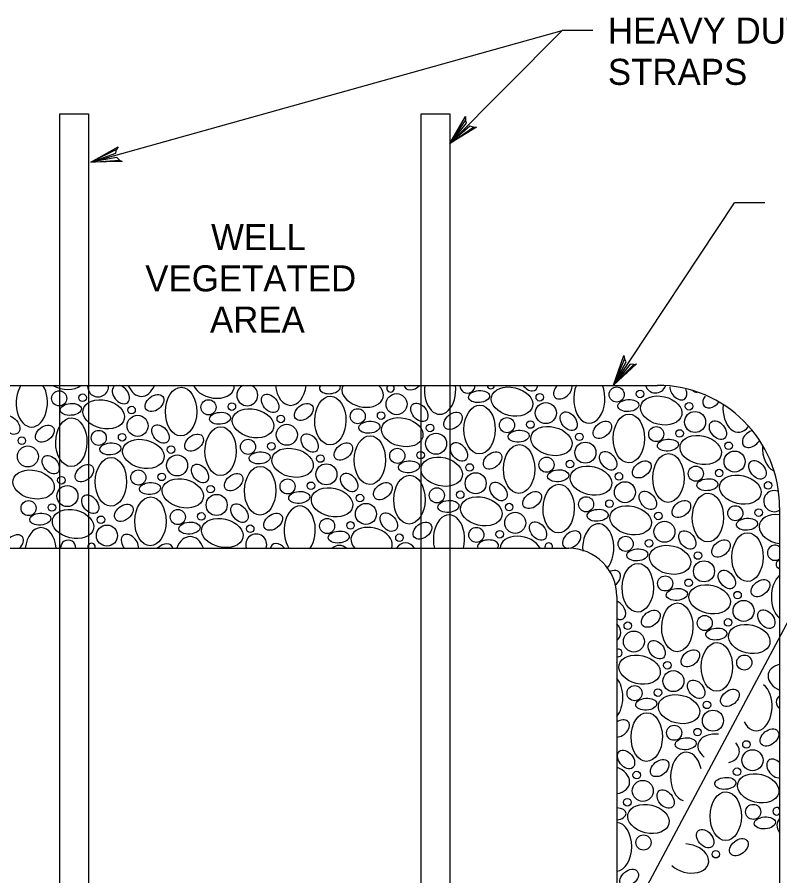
# Model space of a CAD drawing. Extents: x 636462 to 637367, y 299944 to 300538.
# Drawn here: x 636795.7 to 636883.5, y 300304.9 to 300403.7 of the extents above; entities that cross this region are included whole.
import ezdxf

# ---------------------------------------------------------------- set-up
doc = ezdxf.new("R2010")
doc.units = 0
doc.layers.add('Default', color=7, linetype='Continuous')

msp = doc.modelspace()

# ---------------------------------------------------------------- linework, layer by layer
at = {"layer": 'Default'}
for p, q in [((636804.179, 300386.976), (636858.441, 300402.116)), ((636845.491, 300389.125), (636858.441, 300402.116)), ((636861.939, 300402.116), (636858.441, 300402.116)), ((636864.326, 300361.299), (636878.253, 300382.304)), ((636881.751, 300382.304), (636878.253, 300382.304)), ((636865.698, 300299.031), (636894.027, 300352.145)), ((636786.81, 300342.561), (636859.157, 300342.561)), ((636800.614, 300342.561), (636803.895, 300342.561)), ((636842.21, 300342.561), (636845.491, 300342.561)), ((636864.722, 300336.996), (636864.722, 300303.181))]:
    msp.add_line(p, q, dxfattribs=at)
for points in [[(636800.614, 300342.561), (636800.614, 300392.536), (636803.895, 300392.536), (636803.895, 300342.561)], [(636842.21, 300342.561), (636842.21, 300392.536), (636845.491, 300392.536), (636845.491, 300342.561)], [(636848.209, 300390.986), (636848.557, 300391.021), (636845.491, 300389.125), (636848.209, 300390.986), (636847.805, 300391.106), (636845.491, 300389.125), (636847.427, 300391.469), (636847.287, 300391.862), (636845.491, 300389.125), (636847.303, 300392.241), (636847.287, 300391.862)], [(636807.465, 300387.201), (636807.783, 300387.055), (636804.179, 300386.976), (636807.465, 300387.201), (636807.179, 300387.51), (636804.179, 300386.976), (636807.037, 300388.014), (636807.115, 300388.424), (636804.179, 300386.976), (636807.322, 300388.742), (636807.115, 300388.424)], [(636866.664, 300363.681), (636866.998, 300363.783), (636864.354, 300361.332), (636866.664, 300363.681), (636866.244, 300363.722), (636864.354, 300361.332), (636865.804, 300364.005), (636865.59, 300364.364), (636864.354, 300361.332), (636865.534, 300364.739), (636865.59, 300364.364)], [(636776.561, 300361.299), (636869.406, 300361.299)], [(636883.459, 300347.245), (636883.459, 300282.226)], [(636800.614, 300286.91), (636800.614, 300342.561)], [(636803.895, 300342.561), (636803.895, 300286.91)], [(636842.21, 300286.91), (636842.21, 300342.561)], [(636845.491, 300342.561), (636845.491, 300286.91)]]:
    msp.add_lwpolyline(points, dxfattribs=at)
for centre, radius in [((636800.529, 300359.801), 0.869), ((636803.221, 300359.874), 0.435), ((636839.363, 300359.135), 1.211), ((636855.85, 300359.924), 0.435), ((636864.705, 300360.241), 0.869), ((636867.396, 300360.314), 0.435), ((636817.712, 300358.773), 0.869), ((636856.545, 300358.107), 1.211), ((636873.032, 300358.896), 0.435), ((636808.856, 300358.456), 0.435), ((636820.403, 300358.846), 0.435), ((636834.894, 300357.745), 0.869), ((636809.552, 300356.639), 1.211), ((636826.038, 300357.428), 0.435), ((636837.585, 300357.818), 0.435), ((636852.076, 300356.717), 0.869), ((636873.727, 300357.078), 1.211), ((636826.734, 300355.61), 1.211), ((636843.221, 300356.4), 0.435), ((636854.767, 300356.789), 0.435), ((636869.258, 300355.688), 0.869), ((636796.227, 300354.932), 0.435), ((636805.082, 300355.249), 0.869), ((636807.773, 300355.321), 0.435), ((636843.916, 300354.582), 1.211), ((636860.403, 300355.372), 0.435), ((636871.949, 300355.761), 0.435), ((636822.264, 300354.22), 0.869), ((636824.955, 300354.293), 0.435), ((636861.098, 300353.554), 1.211), ((636877.585, 300354.343), 0.435), ((636796.922, 300353.114), 1.211), ((636813.409, 300353.904), 0.435), ((636839.446, 300353.192), 0.869), ((636842.137, 300353.265), 0.435), ((636878.28, 300352.526), 1.211), ((636814.104, 300352.086), 1.211), ((636830.591, 300352.875), 0.435), ((636856.628, 300352.164), 0.869), ((636859.319, 300352.237), 0.435), ((636809.635, 300350.696), 0.869), ((636831.286, 300351.058), 1.211), ((636847.773, 300351.847), 0.435), ((636873.81, 300351.136), 0.869), ((636876.501, 300351.209), 0.435), ((636800.779, 300350.379), 0.435), ((636812.326, 300350.769), 0.435), ((636826.817, 300349.668), 0.869), ((636848.468, 300350.03), 1.211), ((636864.955, 300350.819), 0.435), ((636801.475, 300348.562), 1.211), ((636817.962, 300349.351), 0.435), ((636829.508, 300349.741), 0.435), ((636843.999, 300348.64), 0.869), ((636865.65, 300349.001), 1.211), ((636882.137, 300349.791), 0.435), ((636818.657, 300347.533), 1.211), ((636835.144, 300348.323), 0.435), ((636846.69, 300348.712), 0.435), ((636861.181, 300347.612), 0.869), ((636797.005, 300347.172), 0.869), ((636799.696, 300347.244), 0.435), ((636835.839, 300346.505), 1.211), ((636852.326, 300347.295), 0.435), ((636863.872, 300347.684), 0.435), ((636878.363, 300346.583), 0.869), ((636814.187, 300346.143), 0.869), ((636816.878, 300346.216), 0.435), ((636853.021, 300345.477), 1.211), ((636869.508, 300346.267), 0.435), ((636881.054, 300346.656), 0.435), ((636805.332, 300345.827), 0.435), ((636831.369, 300345.115), 0.869), ((636834.06, 300345.188), 0.435), ((636870.203, 300344.449), 1.211), ((636806.027, 300344.009), 1.211), ((636822.514, 300344.798), 0.435), ((636848.551, 300344.087), 0.869), ((636851.242, 300344.16), 0.435), ((636839.696, 300343.77), 0.435), ((636865.733, 300343.059), 0.869), ((636868.424, 300343.132), 0.435), ((636874.06, 300341.714), 0.435), ((636874.755, 300339.896), 1.211), ((636870.286, 300338.506), 0.869), ((636872.977, 300338.579), 0.435), ((636878.613, 300337.161), 0.435), ((636879.308, 300335.344), 1.211), ((636874.838, 300333.954), 0.869), ((636865.983, 300333.637), 0.435), ((636877.53, 300334.027), 0.435), ((636866.679, 300331.819), 1.211), ((636879.391, 300329.401), 0.869), ((636870.536, 300329.084), 0.435), ((636871.231, 300327.267), 1.211), ((636866.761, 300325.877), 0.869), ((636869.453, 300325.95), 0.435), ((636875.088, 300324.532), 0.435), ((636875.784, 300322.714), 1.211), ((636871.314, 300321.324), 0.869), ((636874.005, 300321.397), 0.435), ((636879.641, 300319.979), 0.435), ((636880.336, 300318.162), 1.211), ((636867.011, 300316.455), 0.435), ((636878.558, 300316.845), 0.435), ((636867.707, 300314.637), 1.211), ((636865.928, 300313.32), 0.435), ((636880.419, 300312.219), 0.869), ((636867.79, 300308.695), 0.869), ((636876.117, 300307.35), 0.435)]:
    msp.add_circle(centre, radius, dxfattribs=at)
for centre, radius, start, end in [((636804.999, 300361.191), 1.211, 174.90177, 5.09823), ((636822.181, 300360.163), 1.211, 110.34202, 69.65798), ((636838.668, 300360.952), 0.435, 127.15322, 52.84678), ((636847.523, 300361.269), 0.869, 178.05212, 1.94788), ((636850.214, 300361.342), 0.435, 185.70515, 354.29485), ((636869.175, 300361.631), 1.211, 195.91853, 340.57424), ((636869.406, 300347.245), 14.053, 360, 90), ((636882.832, 300347.973), 1.211, 71.40593, 301.16664), ((636823.209, 300342.981), 1.211, 339.72002, 200.27998), ((636801.558, 300342.619), 0.869, 356.16847, 183.83153), ((636804.249, 300342.692), 0.435, 342.48017, 197.51983), ((636840.391, 300341.953), 1.211, 30.14319, 149.85681), ((636856.878, 300342.742), 0.435, 335.36934, 204.63066), ((636859.157, 300336.996), 5.565, 0, 90), ((636882.915, 300342.031), 0.869, 51.25813, 308.74187), ((636864.9, 300330.502), 0.435, 245.75739, 114.24261), ((636883.944, 300324.849), 0.869, 123.85392, 236.14608), ((636883.11, 300312.292), 0.435, 36.56425, 323.43575)]:
    msp.add_arc(centre, radius, start, end, dxfattribs=at)
for centre, major_axis, ratio, start_param, end_param in [((636797.375, 300359.305), (0.03, 2.806), 0.641702, 0.787152, 5.509543), ((636801.101, 300362.517), (-2.359, 0.554), 0.672414, 1.147145, 2.666394), ((636807.628, 300360.252), (-0.766, 0.938), 0.672414, 5.99084, 11.854683), ((636810.004, 300362.829), (0.03, 2.806), 0.641702, 2.154377, 4.142318), ((636818.283, 300361.489), (-2.359, 0.554), 0.672414, 0.449253, 3.364286), ((636827.186, 300361.801), (0.03, 2.806), 0.641702, 1.757474, 4.53922), ((636831.68, 300361.029), (1.211, 0.089), 0.56568, 2.61181, 6.555696), ((636835.465, 300360.46), (-2.359, 0.554), 0.672414, 6.096692, 10.283218), ((636841.313, 300361.758), (0.938, 0.766), 0.672414, 2.741076, 4.920143), ((636844.368, 300360.773), (0.03, 2.806), 0.641702, 1.388977, 4.907717), ((636854.622, 300361.72), (-0.766, 0.938), 0.672414, 1.473017, 3.806135), ((636858.495, 300360.73), (0.938, 0.766), 0.672414, 1.649549, 6.01167), ((636861.55, 300359.745), (0.03, 2.806), 0.641702, 0.990546, 5.306149), ((636865.276, 300362.957), (-2.359, 0.554), 0.672414, 1.745064, 2.068476), ((636871.804, 300360.692), (-0.766, 0.938), 0.672414, 0.632085, 4.340625), ((636874.18, 300363.269), (0.03, 2.806), 0.641702, 2.733587, 3.036319), ((636875.677, 300359.702), (0.938, 0.766), 0.672414, 1.889372, 5.042471), ((636878.732, 300358.716), (0.03, 2.806), 0.641702, 1.451819, 3.835751), ((636880.23, 300355.149), (0.938, 0.766), 0.672414, 1.079747, 5.140607), ((636883.285, 300354.164), (0.03, 2.806), 0.641702, 1.510505, 2.841114), ((636828.214, 300344.619), (0.03, 2.806), 0.641702, 3.895895, 8.683985), ((636845.397, 300343.591), (0.03, 2.806), 0.641702, 4.34342, 8.23646), ((636883.487, 300344.746), (-2.359, 0.554), 0.672414, 4.880401, 7.99917), ((636862.579, 300342.562), (0.03, 2.806), 0.641702, 3.737484, 7.981271), ((636798.403, 300342.123), (0.03, 2.806), 0.641702, 4.876016, 7.703864), ((636836.493, 300343.278), (-2.359, 0.554), 0.672414, 3.036327, 7.060398), ((636859.523, 300343.548), (0.938, 0.766), 0.672414, 3.88117, 10.008123), ((636795.348, 300343.108), (0.938, 0.766), 0.672414, 4.817614, 9.126791), ((636808.656, 300343.07), (-0.766, 0.938), 0.672414, 3.715208, 7.84713), ((636815.585, 300341.094), (0.03, 2.806), 0.641702, 5.269091, 7.310789), ((636849.89, 300342.819), (1.211, 0.089), 0.56568, 5.772082, 9.67861), ((636853.675, 300342.25), (-2.359, 0.554), 0.672414, 3.663634, 6.433091), ((636812.53, 300342.08), (0.938, 0.766), 0.672414, 5.90753, 8.036875), ((636825.838, 300342.041), (-0.766, 0.938), 0.672414, 4.717091, 6.845247), ((636832.767, 300340.066), (0.03, 2.806), 0.641702, 5.814419, 6.765461), ((636884.254, 300340.762), (1.211, 0.089), 0.56568, 2.24457, 3.95588), ((636864.076, 300338.995), (0.938, 0.766), 0.672414, 4.608656, 7.586126), ((636884.313, 300336.982), (0.03, 2.806), 0.641702, 0.510379, 2.664018), ((636864.755, 300335.433), (-0.766, 0.938), 0.672414, 2.226207, 5.435012), ((636862.78, 300333.145), (-2.359, 0.554), 0.672414, 2.676817, 3.919569), ((636863.548, 300329.161), (1.211, 0.089), 0.56568, 5.990446, 6.493189), ((636884.515, 300327.564), (-2.359, 0.554), 0.672414, 5.326823, 7.552749), ((636863.607, 300325.38), (0.03, 2.806), 0.641702, 3.825571, 5.632012), ((636880.789, 300324.352), (0.03, 2.806), 0.641702, 2.262316, 5.820963), ((636865.104, 300321.813), (0.938, 0.766), 0.672414, 3.845039, 7.717298), ((636876.438, 300319.487), (-2.359, 0.554), 0.672414, 4.879478, 7.232002), ((636876.438, 300319.487), (-2.359, 0.554), 0.672414, 2.24729, 3.888094), ((636872.712, 300316.275), (0.03, 2.806), 0.641702, 5.051826, 9.249691), ((636882.965, 300317.222), (-0.766, 0.938), 0.672414, 4.880204, 9.064201), ((636863.808, 300315.963), (-2.359, 0.554), 0.672414, 2.11988, 4.476506), ((636864.576, 300311.979), (1.211, 0.089), 0.56568, 4.791589, 7.692047), ((636864.635, 300308.198), (0.03, 2.806), 0.641702, 3.20616, 6.251422), ((636885.543, 300310.382), (-2.359, 0.554), 0.672414, 5.929489, 6.950082), ((636872.913, 300306.858), (-2.359, 0.554), 0.672414, 0.843368, 4.968071)]:
    msp.add_ellipse(centre, major_axis=major_axis, ratio=ratio, start_param=start_param, end_param=end_param, dxfattribs=at)
for centre, major_axis, ratio in [((636852.647, 300359.432), (-2.359, 0.554), 0.672414), ((636811.502, 300359.262), (0.938, 0.766), 0.672414), ((636814.557, 300358.277), (0.03, 2.806), 0.641702), ((636824.81, 300359.224), (-0.766, 0.938), 0.672414), ((636848.862, 300360.001), (1.211, 0.089), 0.56568), ((636869.829, 300358.404), (-2.359, 0.554), 0.672414), ((636805.653, 300357.964), (-2.359, 0.554), 0.672414), ((636828.684, 300358.234), (0.938, 0.766), 0.672414), ((636831.739, 300357.248), (0.03, 2.806), 0.641702), ((636841.992, 300358.195), (-0.766, 0.938), 0.672414), ((636866.044, 300358.973), (1.211, 0.089), 0.56568), ((636801.868, 300358.533), (1.211, 0.089), 0.56568), ((636822.835, 300356.936), (-2.359, 0.554), 0.672414), ((636845.866, 300357.206), (0.938, 0.766), 0.672414), ((636848.921, 300356.22), (0.03, 2.806), 0.641702), ((636859.174, 300357.167), (-0.766, 0.938), 0.672414), ((636794.999, 300356.727), (-0.766, 0.938), 0.672414), ((636801.927, 300354.752), (0.03, 2.806), 0.641702), ((636819.05, 300357.505), (1.211, 0.089), 0.56568), ((636840.017, 300355.908), (-2.359, 0.554), 0.672414), ((636866.103, 300355.192), (0.03, 2.806), 0.641702), ((636876.356, 300356.139), (-0.766, 0.938), 0.672414), ((636798.872, 300355.738), (0.938, 0.766), 0.672414), ((636812.181, 300355.699), (-0.766, 0.938), 0.672414), ((636819.109, 300353.724), (0.03, 2.806), 0.641702), ((636836.232, 300356.476), (1.211, 0.089), 0.56568), ((636857.199, 300354.88), (-2.359, 0.554), 0.672414), ((636863.048, 300356.177), (0.938, 0.766), 0.672414), ((636816.054, 300354.709), (0.938, 0.766), 0.672414), ((636829.363, 300354.671), (-0.766, 0.938), 0.672414), ((636836.291, 300352.696), (0.03, 2.806), 0.641702), ((636853.414, 300355.448), (1.211, 0.089), 0.56568), ((636874.381, 300353.852), (-2.359, 0.554), 0.672414), ((636806.421, 300353.98), (1.211, 0.089), 0.56568), ((636810.206, 300353.412), (-2.359, 0.554), 0.672414), ((636833.236, 300353.681), (0.938, 0.766), 0.672414), ((636846.545, 300353.643), (-0.766, 0.938), 0.672414), ((636853.473, 300351.668), (0.03, 2.806), 0.641702), ((636870.596, 300354.42), (1.211, 0.089), 0.56568), ((636799.551, 300352.175), (-0.766, 0.938), 0.672414), ((636823.603, 300352.952), (1.211, 0.089), 0.56568), ((636827.388, 300352.384), (-2.359, 0.554), 0.672414), ((636850.418, 300352.653), (0.938, 0.766), 0.672414), ((636863.727, 300352.615), (-0.766, 0.938), 0.672414), ((636870.656, 300350.639), (0.03, 2.806), 0.641702), ((636806.48, 300350.2), (0.03, 2.806), 0.641702), ((636840.785, 300351.924), (1.211, 0.089), 0.56568), ((636844.57, 300351.355), (-2.359, 0.554), 0.672414), ((636867.6, 300351.625), (0.938, 0.766), 0.672414), ((636880.909, 300351.586), (-0.766, 0.938), 0.672414), ((636797.576, 300349.887), (-2.359, 0.554), 0.672414), ((636803.425, 300351.185), (0.938, 0.766), 0.672414), ((636816.733, 300351.147), (-0.766, 0.938), 0.672414), ((636823.662, 300349.171), (0.03, 2.806), 0.641702), ((636857.967, 300350.896), (1.211, 0.089), 0.56568), ((636861.752, 300350.327), (-2.359, 0.554), 0.672414), ((636814.758, 300348.859), (-2.359, 0.554), 0.672414), ((636820.607, 300350.157), (0.938, 0.766), 0.672414), ((636833.915, 300350.118), (-0.766, 0.938), 0.672414), ((636840.844, 300348.143), (0.03, 2.806), 0.641702), ((636875.149, 300349.868), (1.211, 0.089), 0.56568), ((636878.934, 300349.299), (-2.359, 0.554), 0.672414), ((636810.973, 300349.428), (1.211, 0.089), 0.56568), ((636831.94, 300347.831), (-2.359, 0.554), 0.672414), ((636837.789, 300349.129), (0.938, 0.766), 0.672414), ((636851.097, 300349.09), (-0.766, 0.938), 0.672414), ((636858.026, 300347.115), (0.03, 2.806), 0.641702), ((636804.104, 300347.622), (-0.766, 0.938), 0.672414), ((636811.032, 300345.647), (0.03, 2.806), 0.641702), ((636828.155, 300348.4), (1.211, 0.089), 0.56568), ((636849.122, 300346.803), (-2.359, 0.554), 0.672414), ((636854.971, 300348.1), (0.938, 0.766), 0.672414), ((636868.279, 300348.062), (-0.766, 0.938), 0.672414), ((636875.208, 300346.087), (0.03, 2.806), 0.641702), ((636807.977, 300346.632), (0.938, 0.766), 0.672414), ((636821.286, 300346.594), (-0.766, 0.938), 0.672414), ((636845.337, 300347.371), (1.211, 0.089), 0.56568), ((636866.305, 300345.775), (-2.359, 0.554), 0.672414), ((636872.153, 300347.072), (0.938, 0.766), 0.672414), ((636798.344, 300345.903), (1.211, 0.089), 0.56568), ((636802.129, 300345.335), (-2.359, 0.554), 0.672414), ((636825.159, 300345.604), (0.938, 0.766), 0.672414), ((636838.468, 300345.566), (-0.766, 0.938), 0.672414), ((636862.519, 300346.343), (1.211, 0.089), 0.56568), ((636815.526, 300344.875), (1.211, 0.089), 0.56568), ((636819.311, 300344.307), (-2.359, 0.554), 0.672414), ((636842.341, 300344.576), (0.938, 0.766), 0.672414), ((636855.65, 300344.538), (-0.766, 0.938), 0.672414), ((636879.702, 300345.315), (1.211, 0.089), 0.56568), ((636832.708, 300343.847), (1.211, 0.089), 0.56568), ((636872.832, 300343.51), (-0.766, 0.938), 0.672414), ((636876.705, 300342.52), (0.938, 0.766), 0.672414), ((636879.761, 300341.534), (0.03, 2.806), 0.641702), ((636867.072, 300341.791), (1.211, 0.089), 0.56568), ((636870.857, 300341.222), (-2.359, 0.554), 0.672414), ((636867.131, 300338.01), (0.03, 2.806), 0.641702), ((636877.384, 300338.957), (-0.766, 0.938), 0.672414), ((636875.41, 300336.67), (-2.359, 0.554), 0.672414), ((636881.258, 300337.967), (0.938, 0.766), 0.672414), ((636871.625, 300337.238), (1.211, 0.089), 0.56568), ((636871.684, 300333.457), (0.03, 2.806), 0.641702), ((636881.937, 300334.404), (-0.766, 0.938), 0.672414), ((636868.628, 300334.443), (0.938, 0.766), 0.672414), ((636879.962, 300332.117), (-2.359, 0.554), 0.672414), ((636876.177, 300332.686), (1.211, 0.089), 0.56568), ((636869.308, 300330.88), (-0.766, 0.938), 0.672414), ((636876.236, 300328.905), (0.03, 2.806), 0.641702), ((636873.181, 300329.89), (0.938, 0.766), 0.672414), ((636867.333, 300328.593), (-2.359, 0.554), 0.672414), ((636873.86, 300326.327), (-0.766, 0.938), 0.672414), ((636871.885, 300324.04), (-2.359, 0.554), 0.672414), ((636877.734, 300325.338), (0.938, 0.766), 0.672414), ((636868.1, 300324.609), (1.211, 0.089), 0.56568), ((636868.159, 300320.828), (0.03, 2.806), 0.641702), ((636882.286, 300320.785), (0.938, 0.766), 0.672414), ((636872.653, 300320.056), (1.211, 0.089), 0.56568), ((636865.783, 300318.251), (-0.766, 0.938), 0.672414), ((636869.657, 300317.261), (0.938, 0.766), 0.672414), ((636880.99, 300314.935), (-2.359, 0.554), 0.672414), ((636877.205, 300315.503), (1.211, 0.089), 0.56568), ((636870.336, 300313.698), (-0.766, 0.938), 0.672414), ((636877.264, 300311.723), (0.03, 2.806), 0.641702), ((636868.361, 300311.411), (-2.359, 0.554), 0.672414), ((636881.758, 300310.951), (1.211, 0.089), 0.56568), ((636874.888, 300309.145), (-0.766, 0.938), 0.672414), ((636878.762, 300308.156), (0.938, 0.766), 0.672414), ((636866.132, 300304.631), (0.938, 0.766), 0.672414)]:
    msp.add_ellipse(centre, major_axis=major_axis, ratio=ratio, dxfattribs=at)

# ---------------------------------------------------------------- texts
for s, height, p in [('HEAVY DUTY LIFTING', 2.99804, (636863.688, 300400.617)), ('STRAPS', 2.998, (636863.688, 300395.871)), ('WELL', 2.998, (636818.013, 300376.855)), ('VEGETATED', 2.998, (636810.435, 300372.109)), ('AREA', 2.998, (636817.883, 300367.362))]:
    msp.add_text(s, height=height, dxfattribs=at).set_placement(p)

doc.saveas('drawing.dxf')
